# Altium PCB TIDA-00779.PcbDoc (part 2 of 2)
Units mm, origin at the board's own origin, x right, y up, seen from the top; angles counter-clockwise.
Board outline 200 x 145 mm, 2 copper layers (Top Layer, Bottom Layer), stack 1.57 mm thick; 147 components, 60 nets, 299 pads, 545 vias.
Unrouted connection lines stored in the file: 4.
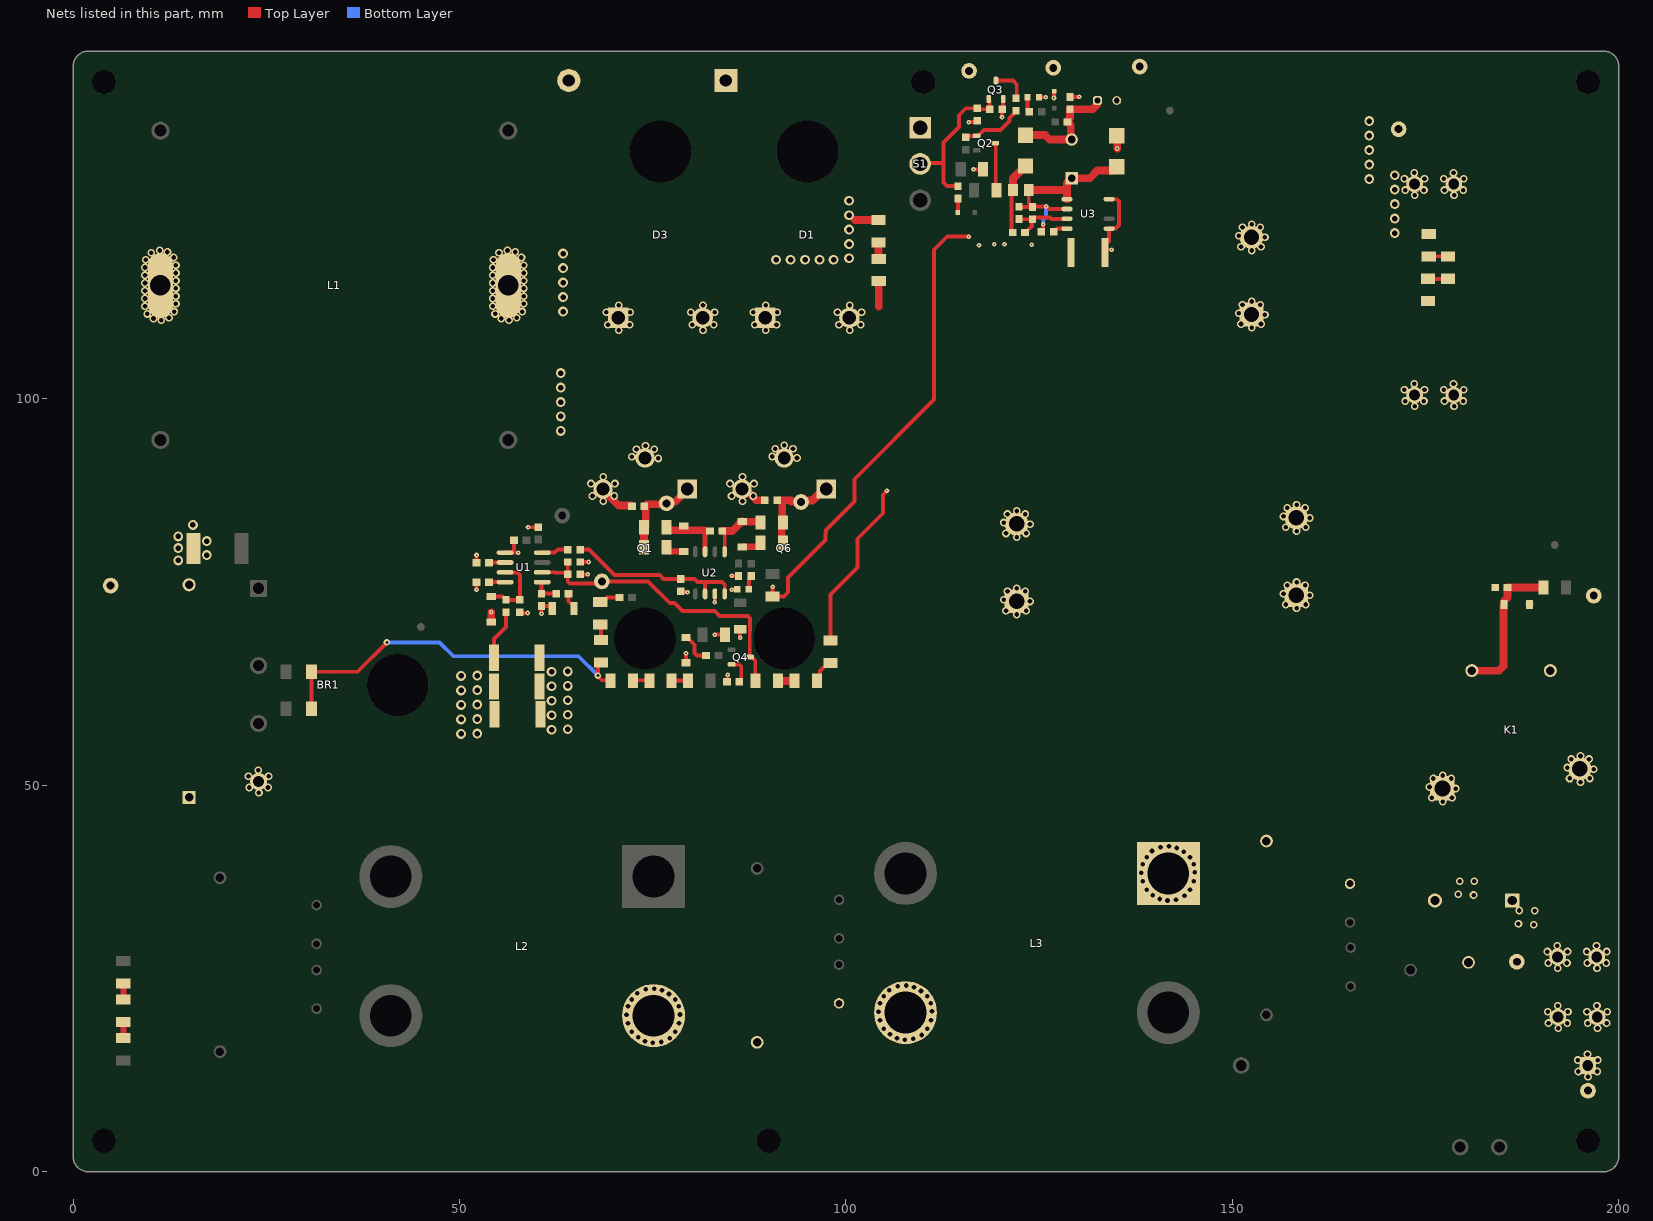
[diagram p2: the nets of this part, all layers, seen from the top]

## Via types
v1: diameter 1, hole 0.6, Top Layer to Bottom Layer, 423 vias
v2: diameter 1.27, hole 0.711, Top Layer to Bottom Layer, 82 vias
v3: diameter 0.6, hole 0.2, Top Layer to Bottom Layer, 38 vias
v4: diameter 0.864, hole 0.406, Top Layer to Bottom Layer, 2 vias

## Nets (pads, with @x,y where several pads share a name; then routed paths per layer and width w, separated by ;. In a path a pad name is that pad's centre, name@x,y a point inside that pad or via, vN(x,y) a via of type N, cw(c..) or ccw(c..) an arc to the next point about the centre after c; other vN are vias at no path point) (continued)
NetC2_2: C2.2 C6.2 L2.4 L3.3
  other v1: 75,16.7 76.1,16.8 74,16.9 107.6,17.1 108.7,17.2 77.2,17.3 106.6,17.3 73.1,17.4 109.8,17.7 105.7,17.8 72.3,18.1 77.9,18.1 104.9,18.5 110.5,18.5 71.8,19.2 78.4,19.2 104.4,19.6 111,19.6 71.6,20.3 71.6,20.3 78.53,20.354 104.2,20.7 104.2,20.7 111.13,20.754 71.8,21.4 78.38,21.404 104.4,21.8 110.98,21.804 72.3,22.3 77.9,22.3 104.9,22.7 110.5,22.7 77.1,23 73,23.1 109.7,23.4 76.2,23.5 105.6,23.5 74.1,23.6 75.2,23.7 108.8,23.9 106.7,24 107.8,24.1
NetC3_2: C3.2 D2.2 L1.S R2.2 TP3.1
  other v1: 11.4,110.2 10.4,110.4 12.4,110.5 9.6,111 13.1,111.3 9.3,112 13.3,112.3 9.3,113 13.3,113.3 9.3,114 13.3,114.3 9.3,115 13.3,115.3 9.3,116 13.3,116.3 9.3,117 13.3,117.3 9.4,118 13,118.3 10.1,118.9 12.2,119 11.2,119.2
  other v2: 13.6,79.1 17.3,79.8 13.6,80.7 17.3,81.6 13.6,82.2 15.5,83.7
NetC10_1: C10.1 U1.2 | length 2.1
  Top Layer w0.5: C10.1@53.8,78.8 53.818,78.817 55.882,78.817 U1.2@55.9,78.835
NetC13_1: C13.1 R10.2 U1.5 | length 3.4
  Top Layer w0.5: U1.5@60.6,76.295 60.6,74.775 60.625,74.8 R10.2@62.5,74.8
NetC14_2: C14.2 R10.1 | length 2.3
  Top Layer w0.5: R10.1@64.1,74.8 64.1,73.793 64.393,73.5 64.575,73.5 64.8,73.275 C14.2@64.8,72.9
NetC15_1: C15.1 D4.1 R11.1 U1.3 | length 9.1
  Top Layer w0.5: D4.1@54.1,74.437 55.588,74.437 56,74.025 R11.1@56,74 C15.1@57.8,74 57.8,77.2 57.454,77.546 55.919,77.546 U1.3@55.9,77.565
NetC17_1: C17.1 D10.1 K1.3 R33.2 | length 19.4
  Top Layer w1: K1.3@180.974,64.845 184.477,64.845 185.063,65.431 185.063,73.251 185.163,73.351 185.163,73.863 185.6,74.3 C17.1@185.6,75.6 R33.2@190.25,75.6
NetC21_2: C21.2 R28.1 | length 2.1
  Top Layer w1: C21.2@104.2,120.25 104.218,120.232 104.218,118.145 R28.1@104.236,118.127
NetC24_1: C24.1 Q3.1 R17.2 R19.1 S1.2 | length 20.5
  Top Layer w0.5: S1.2@109.6,130.4 109.7,130.5 112.6,130.5 ; R19.1@114.5,127.525 113.075,127.525 112.6,128 112.6,130.5 ; Q3.1@118.45,138.8 118.6,138.65 C24.1@118.6,137.475 117.125,137.475 R17.2@117,137.6 115.493,137.6 114.6,136.707 114.6,135.2 112.6,133.2 112.6,130.5
NetC27_1: C27.1 R43.2 U2.2 U2.4 | length 23.4
  Top Layer w0.5: R43.2@65.6,80.5 66.733,80.5 70.033,77.2 75.9,77.2 76.4,76.7 C27.1@78.6,76.7 80.424,76.7 80.806,76.318 81.538,76.318 ; U2.2@81.765,74.775 81.765,76.09 81.538,76.318 ; U2.4@84.305,74.775 84.305,75.995 83.982,76.318 81.538,76.318
NetC29_1: C29.1 R46.1 R47.2 U3.3 | length 8.5
  Top Layer w0.5: R47.2@122.377,123.264 122.391,123.25 124.109,123.25 C29.1@124.123,123.236 ; R46.1@123.164,121.523 123.189,121.523 124.043,122.377 124.043,123.157 C29.1@124.123,123.236 ; U3.3@128.598,123.301 126.56,123.301 126.4,123.461 124.348,123.461 C29.1@124.123,123.236
NetC29_2: C29.2 C30.2 C31.2 D15.1 L5.1 R47.1 U3.1 U3.2 | length 26.6
  Top Layer w0.5: R47.1@122.377,124.864 122.391,124.85 C29.2@124.109,124.85 ; C31.2@123.639,127.036 123.639,125.345 C29.2@124.123,124.861 ; C29.2@124.167,124.881 125.881,124.881 v3(125.9,124.9) 125.927,124.9 126.256,124.571 U3.2@128.598,124.571 ; C30.2@125.264,121.623 125.481,121.84 125.481,122.581 v3(125.5,122.6)
  Top Layer w1: C31.2@123.639,127.036 128.551,127.036 128.598,126.99 ; U3.1@128.598,125.841 128.598,126.99 ; D15.1@135.023,130.036 134.542,129.556 132.523,129.556 131.516,128.55 L5.1@129.197,128.55 128.598,127.95 128.598,126.99
  Bottom Layer w0.5: v3(125.5,122.6) 125.519,122.619 125.519,123.146 125.9,123.527 v3(125.9,124.9)
NetC30_1: C30.1 U3.4 | length 1.9
  Top Layer w0.5: C30.1@126.864,121.623 126.889,121.623 127.297,122.031 U3.4@128.598,122.031
NetC31_1: C31.1 D13.1 R46.2 | length 9.4
  Top Layer w0.5: R46.2@121.564,121.523 121.402,121.684 121.402,126.832 C31.1@121.607,127.036
  Top Layer w1: C31.1@121.607,127.036 121.607,128.52 D13.1@123.223,130.136
NetC32_1: C32.1 D13.2 L5.2 R48.2 R50.1 | length 14.5
  Top Layer w1: D13.2@123.223,134.136 125.778,134.136 126.364,133.55 L5.2@129.197,133.55 129.082,133.664 129.082,135.404 R50.1@128.664,135.823 ; R50.1@128.773,136.132 128.977,136.336 R48.2@128.977,137.464 131.891,137.464 132.477,138.05 132.477,138.547 C32.1@132.54,138.609
NetD1_2: D1.2 D3.2 L1.N Q1.2 Q6.2 R28.2 | length 3.3
  Top Layer w1: 104.236,111.936 R28.2@104.236,115.227
  other v1: 75.708,92.3 93.658,92.357 72.3,92.5 90.45,92.556 72.9,93.5 75.2,93.5 90.85,93.556 93.15,93.556 74.05,93.944 92,94 81.5,108.9 100.5,108.9 80.1,109.6 82.9,109.6 99.1,109.6 101.9,109.6 56.4,110.2 55.4,110.4 57.4,110.5 54.6,111 79.9,111.2 83,111.2 98.9,111.2 102,111.2 58.1,111.3 54.3,112 81.5,112.1 100.5,112.1 58.3,112.3 54.3,113 58.3,113.3 54.3,114 58.3,114.3 54.3,115 58.3,115.3 54.3,116 58.3,116.3 54.3,117 58.3,117.3 54.4,118 58,118.3 55.1,118.9 57.2,119 56.2,119.2
  other v2: 63.1,95.85 63.1,97.725 63.1,99.6 63.1,101.475 63.1,103.35 63.4,111.3 63.4,113.175 63.4,115.05 63.4,116.925 63.4,118.8
NetD5_1: D5.1 R13.2 | length 1.8
  Top Layer w0.5: D5.1@87.427,75.364 87.427,76.743 87.736,77.052 R13.2@87.736,77.077
NetD6_1: D6.1 D7.1 R20.2 R25.2 | length 49
  Top Layer w0.5: D7.1@30.85,59.9 D6.1@30.85,64.7 36.8,64.7 v4(40.6,68.5) ; R25.2@68.3,65.9 67.9,65.5 v4(67.9,64.2) 67.9,64.102 68.4,63.602 68.4,63.6 R20.2@69.55,63.6
  Bottom Layer w0.5: v4(40.6,68.5) 47.4,68.5 49.2,66.7 65.4,66.7 v4(67.9,64.2)
NetD8_2: D8.2 R23.1 | length 4.2
  Top Layer w0.5: D8.2@79.3,69.137 79.453,69.137 80.4,68.19 80.4,67.093 80.693,66.8 R23.1@81.9,66.8
NetD9_2: D9.2 R19.2 | length 1.8
  Top Layer w0.5: D9.2@114.466,124.125 114.5,124.159 R19.2@114.5,125.925
NetD11_1: D11.1 R3.1 R44.1 U2.7 | length 8
  Top Layer w0.6: 81.75,82.9 81.765,82.885 U2.7@81.765,80.225
  Top Layer w1: R3.1@76.75,83.4 76.75,83.15 76.9,83 81.65,83 81.75,82.9
NetD11_2: D11.2 R24.1 | length 2.6
  Top Layer w0.8: R24.1@76.75,80.8 76.75,80.525 77.013,80.262 D11.2@79,80.262
NetD12_1: D12.1 R40.1 R44.2 U2.5 | length 8.2
  Top Layer w0.5: R44.2@84,82.9 84.025,82.9 84.305,82.62 U2.5@84.305,80.225
  Top Layer w1: R44.2@84.025,82.9 85.295,82.9 86.533,84.138 D12.1@86.6,84.138 86.643,84.095 88.755,84.095 R40.1@88.85,84
NetD12_2: D12.2 R41.1 | length 2.7
  Top Layer w0.8: D12.2@86.6,80.863 88.688,80.863 88.95,81.125 R41.1@88.95,81.4
NetD16_1: D16.1 R31.1 | length 2
  Top Layer w0.5: D16.1@123.473,139.036 123.473,137.361 123.698,137.136 R31.1@123.723,137.136
NetF1_1: F1.1 P1.1 TP1.1
  other v1: 196.011,12.301 194.761,12.976 197.186,12.976 194.661,14.451 197.261,14.451 195.936,15.201 192.151,18.568 197.231,18.568 190.901,19.243 193.326,19.243 195.981,19.243 198.406,19.243 190.801,20.718 193.401,20.718 195.881,20.718 198.481,20.718 192.076,21.468 197.156,21.468
NetQ1_1: Q1.1 R1.2 R3.2 R24.2 TP7.1 | length 11.8
  Top Layer w1: R24.2@73.85,80.8 73.85,82.975 R3.2@73.85,83.4 ; R1.2@73.9,86.1 74,86.1 R1.2@74.1,86.2 ; R3.2@74.1,83.45 R1.2@74.1,86.2 ; Q1.1@79.45,88.239 77.894,86.682 76.98,86.682 76.664,86.367 74.267,86.367 R1.2@74.1,86.2
NetQ2_1: Q2.1 R15.2 R16.1 | length 8.3
  Top Layer w0.5: R15.2@115.5,133.85 115.65,134 116.85,134 Q2.1@116.9,134.05 117.1,134.05 117.85,134.8 120,134.8 121.168,135.968 121.168,136.343 122.1,137.275 R16.1@122.1,137.3
NetQ2_3: Q2.3 R18.1 | length 6.2
  Top Layer w0.5: Q2.3@119.3,133.09 Q2.3@119.3,133.1 119.325,133.1 119.375,133.05 119.375,127.075 R18.1@119.45,127
NetQ3_3: Q3.3 R16.2 | length 4.7
  Top Layer w0.5: Q3.3@119.4,141.2 121.6,141.2 122.1,140.7 R16.2@122.1,138.9
NetQ4_2: Q4.2 R14.2 | length 3.4
  Top Layer w0.5: Q4.2@85.2,65.65 86.157,65.65 86.45,65.357 86.45,63.625 86.225,63.4 R14.2@86.2,63.4
NetQ6_1: Q6.1 R40.2 R41.2 R42.2 TP4.1 | length 12
  Top Layer w1: R42.2@91.3,86.9 91.75,86.9 ; R40.2@91.7,83.844 91.7,81.55 R41.2@91.85,81.4 ; R40.2@91.75,84 91.75,86.9 ; 92.9,86.7 94.149,86.7 TP4.1@94.187,86.662 94.384,86.86 95.671,86.86 Q6.1@97.15,88.338 ; 92.9,86.9 91.75,86.9
NetR6_1: R6.1 R7.2 | length 3.2
  Top Layer w0.5: R7.2@96.25,63.5 96.65,63.9 96.65,64.775 97.725,65.85 R6.1@98,65.85
NetR7_1: R7.1 R8.2 | length 2.2
  Top Layer w1: R8.2@91.2,63.525 91.212,63.513 93.337,63.513 R7.1@93.35,63.5
NetR12_2: R12.2 U1.4 | length 2.1
  Top Layer w0.5: R12.2@53.8,76.3 53.802,76.297 55.898,76.297 U1.4@55.9,76.295
NetR20_1: R20.1 R21.2 | length 2.1
  Top Layer w0.5: R20.1@72.45,63.6 74.495,63.6 R21.2@74.552,63.544
NetR21_1: R21.1 R22.2 | length 2.1
  Top Layer w0.5: R21.1@77.452,63.544 79.494,63.544 R22.2@79.55,63.6
NetR25_1: R25.1 R26.2 | length 2.3
  Top Layer w0.5: R26.2@67.9,70.8 R26.2@68,70.9 ; R26.2@68.2,70.8 68.3,70.7 R25.1@68.3,68.8 R25.1@68.4,68.9
NetR26_1: R26.1 R38.2 | length 2.7
  Top Layer w0.5: R26.1@68.2,73.7 68.475,73.7 69.075,74.3 R38.2@70.7,74.3
NetR29_1: R29.1 R30.2 | length 2.1
  Top Layer w0.8: R29.1@6.5,17.3 R30.2@6.5,19.4
NetR30_1: R30.1 R32.2 | length 2.1
  Top Layer w0.8: R30.1@6.5,22.3 R32.2@6.5,24.35
NetR34_1: R34.1 R35.2 | length 2.5
  Top Layer w0.5: R34.1@175.4,118.45 R35.2@177.9,118.45
NetR35_1: R35.1 R36.2 | length 2.5
  Top Layer w0.5: R36.2@175.44,115.5 R35.1@177.94,115.5
NetR43_1: R43.1 U1.8 | length 3.6
  Top Layer w0.5: U1.8@60.6,80.105 62.305,80.105 62.7,80.5 R43.1@64,80.5
PGND: C4.1 C5.1 C10.2 C11.2 C12.2 C13.2 C14.1 C15.2 C16.2 C17.2 C18.1 C19.2 C20.2 C24.2 C25.2 C27.2 C28.1 C32.2 C33.1 D4.2 D5.2 D8.1 D10.2 D14.2 D15.2 D16.2 K1.4 P5.1 Q1.3 Q3.2 Q6.3 R1.1 R4.1 R5.1 R9.1 R12.1 R14.1 R17.1 R27.1 R36.1 R42.1 R45.1 R48.1 S1.1 TP6.1 TP10.1 TP11.1 TP12.1 U1.1 U2.3 | length 99.9
  Top Layer w0.5: v3(52.2,75.3) R12.1@52.2,76.3 ; C10.2@52.2,78.8 v3(52.2,79.8) ; U1.1@55.9,80.105 U1.1@56.905,80.105 ; U1.1@56.673,80.1 56.702,80.1 57.05,80.448 C12.2@57.05,81.7 ; 57.05,80.1 v3(57.6,80.1) ; C15.2@57.8,72.4 57.9,72.3 v3(58.8,72.3) ; v3(58.859,83.4) C16.2@60.2,83.4 ; v3(60.6,72.2) C13.2@60.6,73.2 61.775,73.2 62,72.975 C14.1@62,72.9 ; C11.2@65.6,77.3 v3(66.6,77.3) ; R9.1@65.6,78.9 v3(66.7,78.9) ; C27.2@78.6,75.1 78.681,75.019 79.481,75.019 v3(79.5,75) ; 79.3,66.4 v3(79.3,67.1) ; v3(83,69.5) C20.2@84.35,69.5 ; v3(83,73.7) 83.017,73.718 83.017,74.757 U2.3@83.035,74.775 ; R14.1@84.6,63.4 84.681,63.481 84.681,64.281 v3(84.7,64.3) ; v3(85.2,75.3) 85.219,75.319 85.883,75.319 D5.2@85.927,75.364 ; v3(85.2,77.1) C28.1@86.1,77.1 ; v3(86.3,69.1) C25.2@86.3,70.2 ; v3(90.5,75.7) R27.1@90.5,74.45 91.963,74.45 92.5,74.987 92.5,76.9 97.35,81.75 97.35,82.75 97.4,82.8 97.4,83.033 101.1,86.733 101.1,89.6 111.4,99.9 111.4,119.3 113.1,121 v3(115.9,121) ; v3(115.9,135.8) 115.919,135.819 116.819,135.819 R17.1@117,136 ; v3(116.5,129.7) C19.2@117.75,129.7 ; v3(120.19,136.465) 120.2,136.475 120.2,137.55 120.3,137.65 120.3,138.75 Q3.2@120.35,138.8 ; D16.2@124.973,139.036 v3(125.864,139.036) ; v3(126.909,138.931) 126.909,139.75 D14.2@126.959,139.8 ; R48.1@128.977,139.064 130.164,139.064 v3(130.2,139.1)
  Top Layer w1: D4.2@54.1,71.162 v3(54.1,72.4) ; Q1.3@68.55,88.239 70.588,86.2 72.2,86.2 R1.1@72.3,86.1 ; Q6.3@86.55,88.343 86.956,88.343 88.399,86.9 R42.1@89.5,86.9 ; D15.2@135.023,134.036 135.1,133.959 v3(135.1,132.4)
  other v1: 122.1,72.1 120.7,72.6 123.3,72.6 158.3,72.9 156.9,73.4 159.5,73.4 123.8,73.8 120.4,74 160,74.6 156.6,74.8 120.9,75.1 123.2,75.1 122.1,75.5 157.1,75.9 159.4,75.9 158.3,76.3 68.6,86.744 86.6,86.743 67.2,87.444 70,87.444 85.2,87.444 88,87.444 67,89.044 70.1,89.044 85,89.043 88.1,89.043 68.6,89.944 86.6,89.944 173.6,99.043 178.68,99.043 172.35,99.718 174.775,99.718 177.43,99.718 179.855,99.718 172.25,101.193 174.85,101.193 177.33,101.193 179.93,101.193 173.525,101.943 178.605,101.943 152.5,109.2 151.1,109.7 153.7,109.7 154.2,110.9 150.8,111.1 151.3,112.2 153.6,112.2 152.5,112.6
  other v2: 61.9,57.2 64,57.25 61.9,59.075 64,59.125 61.9,60.95 64,61 61.9,62.825 64,62.875 61.9,64.7 64,64.75
  other v3: 117.2,119.9 124.041,119.959 119.2,120 120.5,120
RLY-N: C1.1 C9.2 K1.1 L3.1 RT1.2 | length 12.3
  Top Layer w0.254: K1.1@175.845,48.357 176.039,48.551 v1@176.039,47.955 ; K1.1@177.164,49.605 178.245,49.605 K1.1@178.345,49.705 ; K1.1@177.199,49.605 177.245,49.559 v1@177.245,47.857 ; K1.1@177.245,49.605 v1@177.245,51.257 ; K1.1@178.445,49.705 178.797,49.705 v1@178.945,49.557
  Bottom Layer w0.254: v1@177.245,47.857 177.174,47.786 177.174,49.595 K1.1@177.164,49.605 178.245,49.605 K1.1@178.345,49.705 ; K1.1@177.245,49.605 v1@177.245,51.257 ; K1.1@178.445,49.705 178.797,49.705 v1@178.945,49.557 ; K1.1@176.039,48.551 175.845,48.357 K1.1@176.039,48.551 ; K1.1@176.039,48.551 176.039,48.709 K1.1@176.039,48.551
  other v1: 141.6,35.1 142.7,35.2 140.6,35.3 143.8,35.7 139.7,35.8 181.2,35.8 179.2,35.9 138.9,36.5 144.5,36.5 138.4,37.6 145,37.6 179.4,37.6 181.3,37.6 138.2,38.7 138.2,38.7 145.13,38.754 138.4,39.8 144.98,39.804 138.9,40.7 144.5,40.7 143.7,41.4 139.6,41.5 142.8,41.9 140.7,42 141.8,42.1 177.2,47.882 175.8,48.382 178.4,48.382 178.9,49.582 175.5,49.782 176,50.882 178.3,50.882 177.2,51.282
RLY-P: K1.2 P2.1 RT1.1 RV1.1 TP2.1 | length 15.4
  Top Layer w0.254: v1(193.625,50.897) 193.66,50.897 K1.2@193.866,51.103 ; v1@193.819,50.495 193.866,50.542 K1.2@193.866,51.103 ; v1(195.025,50.397) 194.984,50.357 194.984,52.104 K1.2@194.944,52.145 ; v1(195.025,53.797) 194.984,53.757 194.984,52.316 194.984,52.186 K1.2@194.944,52.145 ; K1.2@195.044,52.316 v1(196.125,53.397) ; K1.2@193.866,51.103 194.908,52.145 K1.2@194.944,52.145
  Bottom Layer w0.254: v1(193.625,50.897) 193.66,50.897 K1.2@193.866,51.103 ; v1@193.819,50.495 193.866,50.542 K1.2@193.866,51.103 ; v1(195.025,50.397) 194.984,50.357 194.984,50.211 194.984,52.104 K1.2@194.944,52.145 ; v1(195.025,53.797) 194.984,53.757 194.984,52.316 194.984,52.186 K1.2@194.944,52.145 ; K1.2@195.044,52.316 v1(196.125,53.397) ; K1.2@193.866,51.103 194.908,52.145 K1.2@194.944,52.145
  other v1: 192.1,26.343 197.18,26.343 190.85,27.018 193.275,27.018 195.93,27.018 198.355,27.018 190.75,28.493 193.35,28.493 195.83,28.493 198.43,28.493 192.025,29.243 197.105,29.243 189,31.98 187,32.08 189.1,33.78 187.1,33.8 196.225,50.897 196.725,52.097 193.325,52.297 193.825,53.397
RTN: BR1.4 C3.1 R4.2 R5.2 R11.2 R45.2 | length 6.5
  Top Layer w0.5: R45.2@54.45,66.5 54.45,68.95 56,70.5 R11.2@56,72.4
  other v1: 24.04,49.043 22.79,49.718 25.215,49.718 22.69,51.193 25.29,51.193 23.965,51.943
  other v2: 50.2,56.65 52.3,56.7 50.2,58.525 52.3,58.575 50.2,60.4 52.3,60.45 50.2,62.275 52.3,62.325 50.2,64.15 52.3,64.2
VDCBUS: C4.2 C5.2 C18.2 C21.1 C33.2 D1.1 D2.1 D3.1 P4.1 R6.2 R34.2 TP5.1 U3.5 U3.8 | length 36
  Top Layer w0.5: R6.2@98,68.75 98,74.7 101.5,78.2 101.5,81.9 104.8,85.2 104.8,87.6 v3(105.3,88.1) ; C33.2@133.523,118.436 133.523,119.886 134.048,120.411 U3.5@134.048,122.031 134.067,122.05 134.85,122.05 135.3,122.5 135.3,125.548 135.007,125.841 U3.8@134.048,125.841 ; C33.2@133.523,119.1 133.723,119.3 v3(134.4,119.3)
  Top Layer w1: 101.17,123.15 C21.1@104.2,123.15
  other v1: 122.1,82.1 120.7,82.6 123.3,82.6 158.3,82.9 156.9,83.4 159.5,83.4 123.8,83.8 120.4,84 160,84.6 156.6,84.8 120.9,85.1 123.2,85.1 122.1,85.5 157.1,85.9 159.4,85.9 158.3,86.3 70.6,108.9 89.6,108.9 69.2,109.6 72,109.6 88.2,109.6 91,109.6 69,111.2 72.1,111.2 88,111.2 91.1,111.2 70.6,112.1 89.6,112.1 152.5,119.2 151.1,119.7 153.7,119.7 154.2,120.9 150.8,121.1 151.3,122.2 153.6,122.2 152.5,122.6 173.6,126.343 178.68,126.343 172.35,127.018 174.775,127.018 177.43,127.018 179.855,127.018 172.25,128.493 174.85,128.493 177.33,128.493 179.93,128.493 173.525,129.243 178.605,129.243
  other v2: 90.95,118 92.825,118 94.7,118 96.575,118 98.4,118 100.4,118.2 100.4,120.025 171,121.45 100.4,121.9 171,123.325 100.4,123.775 171,125.2 100.4,125.65 171,127.075 167.7,128.45 171,128.95 167.7,130.325 167.7,132.2 167.7,134.075 167.7,135.95
VSENSE: C11.1 Q4.3 R8.1 R9.2 TP8.1 U1.6 | length 40.4
  Top Layer w0.5: U1.6@60.6,77.565 62.335,77.565 62.4,77.5 63.8,77.5 C11.1@64,77.3 ; R9.2@64,78.9 C11.1@64,77.3 ; R8.1@88.3,63.525 88.25,63.575 88.25,66.15 87.8,66.6 Q4.3@87.6,66.6 87.55,66.65 87.55,70 87.6,70.05 87.6,71.613 87.307,71.906 83.655,71.906 83.017,72.543 78.857,72.543 77.8,73.6 77.19,73.6 74.405,76.385 TP8.1@68.417,76.385 68.133,76.1 64.293,76.1 64,76.393 C11.1@64,77.3
pads on no net: BR1. D1. D3. FID1.1 FID2.1 FID3.1 L1.1 L1.2 L1.3 L1.4 MP1. MP2. MP3. MP4. MP5. MP6. Q1. Q6. S1.3 U2.1 U2.8 U3.6

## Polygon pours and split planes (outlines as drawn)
RLY-N on Bottom Layer "Bottom Layer-RLY-N" (solid, pour order 147): 179.3,35.3 181.6,35.3 186,39.7 186,53.9 183.8,56.1 144.5,56.1 136,47.6 136,34.8 136.5,34.3 160.7,34.3 161.7,35.3 169,35.3 170.7,33.6 177.6,33.6
NetBR1_2 on Bottom Layer "Bottom Layer-NetBR1_2" (solid, pour order 143): 25.85,63 36.3,63 37.3,64 37.3,68.1 35.1,70.3 21,70.3 3.6,70.3 2.2,70.3 0.9,69 0.9,66.8 1.7,66 18.05,66 21.05,63 25.85,63
VDCBUS on Bottom Layer "Bottom Layer-VDCBUS 1" (solid, pour order 139): 67.6,108.5 74.2,108.5 74.4,108.3 75.1,109 75.1,113.2 77.9,116 85.4,116 86.2,115.2 86.2,108.494 87.794,106.9 93.2,106.9 93.8,107.5 93.8,112.7 97.1,116 101.4,116 104.6,112.8 104.6,106.1 102.9,104.4 107,104.4 108.2,103.2 115,103.2 128,116.2 113.8,116.2 105.136,124.864 101.7,128.3 101.7,141.7 100.1,143.3 73.9,143.3 70.3,139.7 70.3,132.539 67.6,129.839
PGND on Bottom Layer "Bottom Layer-PGND 1" (solid, pour order 119): 152.5,60.1 152.6,60 195.2,60 199,63.8 199,75.8 198.1,76.7 175,76.7 108,76.7 98.1,86.6 95.4,86.6 95.2,86.8 95.2,87.8 94.9,88.1 94.6,88.1 94.4,88.3 90,88.3 87.8,90.5 82.2,90.5 81.7,90 81.7,87.4 80.7,86.4 78.5,86.4 78,86.9 78,88 77.4,88.6 71.7,88.6 69.4,90.9 66.9,90.9 66,90 66,78.6 67.5,77.1 84.3,77.1 88.9,72.5 95.4,72.5 104.8,63.1 66.2,63.1 63.5,65.8 58,65.8 57.8,65.6 57.8,53.6 58.4,53 133.9,53 141,60.1
RLY-P on Bottom Layer "Top Layer-RLY-P" (solid, pour order 129): 184.577,25.575 191.777,25.575 198.677,25.575 199.7,26.597 199.7,54.8 197.6,56.9 188.3,56.9 187.577,56.177 187.577,38.475 182.477,33.375 179.975,33.375 177.677,31.077 177.677,27.623 179.077,26.223 179.725,25.575
NetC1_2 on Bottom Layer "Top Layer-NetC1_2" (solid, pour order 128): 171.577,5.475 177.077,10.975 177.077,23.375 175.777,24.675 136.977,24.675 135.877,23.575 135.877,10.375 140.777,5.475
PGND on Bottom Layer "TOP_LAYER_NONET_P-001" (solid, remove dead copper, pour order 79): 105.7,129.6 115.9,119.4 125.8,119.4 129.7,123.3 129.7,125.014 132.386,127.7 135,127.7 140.7,133.4 140.7,143.2 139.4,144.5 109.1,144.5 105.7,141.1 105.7,138.7
NetD1_2 on Bottom Layer "TOP_LAYER_NONET_P-001" (solid, pour order 134): 97.077,112.575 97.677,113.175 102.477,113.175 103,112.652 103,107.6 102.5,107.1 97.7,107.1 97.077,107.723
NetD1_2 on Bottom Layer "TOP_LAYER_NONET_P-001" (solid, pour order 133): 78.077,112.575 78.677,113.175 83.477,113.175 84,112.652 84,107.6 83.5,107.1 78.7,107.1 78.077,107.723
NetD1_2 on Bottom Layer "TOP_LAYER_NONET_P-001" (solid, pour order 132): 36.118,119.616 36.118,92.933 38.377,90.675 38.403,90.7 62.5,90.7 64.6,92.8 64.6,120.3 62.4,122.5 62.375,122.475 38.977,122.475
NetC3_2 on Bottom Layer "Bottom Layer-No Net 2" (solid, pour order 126): 14.303,143.9 65.927,143.9 67.377,142.313 67.377,134.682 59.926,127.375 31.784,127.375 29.132,124.888 29.236,87.534 26.634,84.931 19.765,84.885 18.377,83.596 18.377,74.658 17.277,73.375 3.677,73.375 2.677,74.375 2.677,132.275
NetF1_1 on Bottom Layer "TOP_LAYER_NONET_P-001" (solid, pour order 127): 179,22 179,8.5 179.525,7.975 198.777,7.975 199.777,8.975 199.777,22.775 199.277,23.275 180.275,23.275
NetC2_1 on Bottom Layer "M1 Board Outline-No Net" (solid, pour order 123): 109.7,50.4 113.077,47.023 113.077,33.975 110.977,31.875 70.477,31.875 68.577,33.775 68.577,48.577 70.4,50.4
NetC2_2 on Bottom Layer "Top Layer-No Net 5" (solid, remove dead copper, pour order 49): 72.4,0.9 108.7,0.9 112.9,5.1 112.9,23.1 111,25 104.9,25 102.1,22.2 91.9,22.2 89.1,25 71.4,25 69,22.6 69,4.3
GNDE on Bottom Layer "TOP_LAYER_NONET_P-001" (solid, pour order 121): 177.1,1 175.8,2.3 178.5,5 186.9,5 188.3,3.6 188.3,1.5 187.8,1
VDCBUS on Bottom Layer "Bottom Layer-VDCBUS" (solid, pour order 115): 186.6,79.8 191.6,84.8 191.6,125.3 180,136.9 147.8,136.9 116.4,105.5 95.7,105.5 93.8,107.4 93.8,112.8 93.2,113.4 86.9,113.4 86.1,112.6 86.1,109.194 87.2,108.094 87.2,105.6 87,105.4 75.5,105.4 75.1,105.8 75.1,112.2 73.4,113.9 68.3,113.9 67.6,113.2 67.6,99.1 70,96.7 95.3,96.7 111.8,80.2 112.2,79.8
PGND on Bottom Layer "Bottom Layer-PGND" (solid, remove dead copper, pour order 98): 109.675,62.775 111.5,64.6 111.5,66.8 107.7,66.8 96.4,78.1 68.3,78.1 67,79.4 67,86.3 66.6,86.7 60.2,86.7 59.5,86 59.5,84.4 59,83.9 50.1,83.9 49.2,83 49.2,70.8 51.5,68.5 65.5,68.5 69.5,64.5 69.5,62.39 69.79,62.1 72,62.1 72,62.5 71.725,62.775
NetBR1_1 on Bottom Layer "NETBR1_1_L02_P084" (solid, pour order 84): 18.6,74.6 20.1,73.1 43.4,73.1 45.7,75.4 45.7,82.2 44.4,83.5 19.3,83.5 18.6,82.8
RTN on Bottom Layer "Top Layer-No Net 1" (solid, pour order 44): 19.8,53.1 26.4,53.1 30.3,57 43,57 44.1,57 46.2,59.1 46.2,64.5 46.9,65.2 56.8,65.2 56.8,49.5 53.1,45.8 50.4,45.8 14.8,45.8 13.5,47.1 13.5,52.3 14.3,53.1 16.4,53.1
NetBR1_3 on Bottom Layer "Bottom Layer-No Net 4" (solid, pour order 42): 37.9,23.4 44.7,23.4 46.7,21.4 46.7,2.4 45.2,0.9 13.9,0.9 0.9,13.9 0.9,62.9 1.9,63.9 15.9,63.9 19.8,60 25.7,60 26.3,59.4 26.3,56.4 25.2,55.3 12.5,55.3 10.6,53.4 10.6,46.8 14.9,42.5 14.9,31.8 26.9,19.8 34.3,19.8
NetBR1_2 on Bottom Layer "Bottom Layer-No Net 3" (solid, pour order 41): 18.6,43.4 45.8,43.4 46.6,42.6 46.6,35.7 44,33.1 18.7,33.1 17,34.8 17,41.8
RLY-N on Top Layer "Top Layer-RLY-N" (solid, pour order 146): 179.3,35.3 181.5,35.3 186,39.8 186,53.9 183.9,56 144.4,56 136,47.6 136,34.1 136.7,33.4 159.8,33.4 161.7,35.3 169,35.3 170.7,33.6 177.6,33.6
PGND on Top Layer "TOP_LAYER_NONET_P-001" (solid, pour order 140): 181.7,60 195.2,60 199,63.8 199,72.6 198.5,73.1 189.1,73.1 187.2,75 187.2,80.8 185.9,82.1 180.3,82.1 178.6,80.4 178.6,61.1 179.3,60.4
NetD1_2 on Top Layer "Bottom Layer-No Net 1" (solid, pour order 125): 92.977,90.875 98.277,96.175 100.477,96.175 106.977,102.675 106.977,112.475 105.477,113.975 97.677,113.975 96.277,112.575 96.277,107.375 94.277,105.375 85.977,105.375 83.977,107.375 83.977,112.675 83.477,113.175 78.677,113.175 78.077,112.575 78.077,106.775 76.577,105.275 66.077,105.275 64.577,106.775 64.577,114.775 64.577,117.811 64.577,120.275 62.377,122.475 52.577,122.475 38.977,122.475 36.118,119.616 36.237,92.814 38.377,90.675 72.677,90.675 74.877,90.675 77.477,93.275 88.177,93.275 90.577,90.875
PGND on Top Layer "TOP_LAYER_NONET_P-001" (solid, pour order 136): 177.3,113.3 188.4,113.3 192.4,109.3 192.4,85.6 186.3,79.5 183.9,79.5 182.1,77.7 181.1,78.7 179,78.7 179,108.6 177.4,110.2
PGND on Top Layer "Top Layer-PGND" (solid, pour order 117): 182.9,78 182.9,108.1 181.1,109.9 177.7,113.3 171.3,113.3 166.1,118.5 166.1,123.4 155.7,133.8 144.8,133.8 139,128 139,117.5 135.7,114.2 130.3,114.2 129.5,115 129.5,120.1 129.1,120.5 117.2,120.5 113.1,116.4 113.1,88.2 105.8,80.9 105.8,72.739 105.7,72.7 105.8,72.6 105.8,64.668 101.392,61.8 67.6,61.8 65.7,63.7 65.7,68.2 58.8,68.2 57.8,67.2 57.8,53.5 58.5,52.8 133.8,52.8 141,60 181.7,60 182.9,61.2
RLY-P on Top Layer "Top Layer-RLY-P" (solid, pour order 104): 184.5,25.6 191.7,25.6 198.6,25.6 199.7,26.7 199.7,54.8 197.6,56.9 188.1,56.9 187.5,56.3 187.5,38.5 182.4,33.4 180,33.4 177.6,31 177.6,27.7 179,26.3 179.7,25.6
NetBR1_3 on Top Layer "TOP_LAYER_NONET_P-001" (solid, pour order 131): 25.7,60 26.3,59.4 26.3,57 24.6,55.3 20.1,55.3 19.3,56.1 19.3,59.5 19.8,60
NetC2_2 on Top Layer "Top Layer-No Net 5" (solid, remove dead copper, pour order 124): 72.477,0.875 108.777,0.875 112.977,5.075 112.977,23.075 111.077,24.975 104.977,24.975 102.177,22.175 91.977,22.175 89.177,24.975 71.477,24.975 69.077,22.575 69.077,4.275
GNDE on Top Layer "TOP_LAYER_NONET_P-001" (solid, pour order 122): 182.45,1 187.8,1 188.3,1.5 188.3,3.6 186.9,5 177.9,5 177.1,4.2 177.1,1.3 177.4,1
VDCBUS on Top Layer "Top Layer-VDCBUS" (solid, pour order 110): 95,116.1 100.3,116.1 101.7,117.5 101.7,141.7 100.1,143.3 73.9,143.3 70.3,139.7 70.3,132.539 67.7,129.939 67.7,109 68.5,108.2 74.3,108.2 75,108.9 75,114.3 76.6,115.9 85.6,115.9 86.1,115.4 86.1,109.2 87,108.3 92.1,108.3 93,109.2 93,114.1
NetC1_2 on Top Layer "Top Layer-NetC1_2" (solid, pour order 101): 171.5,5.5 177,11 177,23.4 175.7,24.7 136.9,24.7 135.8,23.6 135.8,10.4 140.7,5.5
VDCBUS on Top Layer "TOP_LAYER_NONET_P-001" (solid, pour order 102): 170.6,120.7 169.7,121.6 169.7,124.9 165.6,129 165.6,135.6 166.87,136.87 180.03,136.87 187,129.9 187,123.1 184.6,120.7
NetF1_1 on Top Layer "TOP_LAYER_NONET_P-001" (solid, pour order 99): 179,22 179,8.5 179.5,8 198.7,8 199.7,9 199.7,22.8 199.2,23.3 180.3,23.3
NetBR1_1 on Top Layer "TOP_LAYER_NONET_P-001" (solid, pour order 90): 18.6,74.6 20.1,73.1 43.4,73.1 45.7,75.4 45.7,82.2 44.4,83.5 19.3,83.5 18.6,82.8
NetC3_2 on Top Layer "Bottom Layer-No Net 2" (solid, pour order 87): 14.05,143.75 65.927,143.9 67.377,142.313 67.377,134.682 59.926,127.375 31.784,127.375 29.132,124.888 29.236,87.534 26.634,84.931 19.765,84.885 18.377,83.596 18.377,74.773 17.2,73.4 3.6,73.4 2.6,74.4 2.6,132.3
RTN on Top Layer "Top Layer-No Net 1" (solid, pour order 83): 19.8,53.1 28,53.1 31.9,57 43,57 44.1,57 46.2,59.1 46.2,67.8 46.6,68.2 56.9,68.2 56.9,49.4 53.5,46 53.3,45.8 50.4,45.8 14.8,45.8 13.5,47.1 13.5,52.3 14.3,53.1 16.4,53.1
NetBR1_2 on Top Layer "Top Layer-NetBR1_2" (solid, pour order 74): 0.9,27.5 1.7,26.7 21.45,26.7 23.6,28.85 23.6,28.9 28.1,33.4 44.3,33.4 46.6,35.7 46.6,42.6 45.8,43.4 14,43.4 10.6,46.8 10.6,53.4 20.2,63 25.9,63 26.4,63.5 26.4,69.6 25.8,70.2 23.8,70.3 2.2,70.3 0.9,69
NetBR1_3 on Top Layer "Top Layer-No Net 12" (solid, pour order 59): 38.2,22.9 15.6,22.9 11.5,18.8 11.5,3.4 14,0.9 45.2,0.9 46.7,2.4 46.7,21.5 44.8,23.4 38.7,23.4
NetC2_1 on Top Layer "M1 Board Outline-No Net" (solid, pour order 48): 109.6,50.5 113,47.1 113,34 110.9,31.9 70.4,31.9 68.5,33.8 68.5,48.5 70.5,50.5

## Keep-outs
Bottom Layer:
  circle w0.254: c129.197,128.55 r1.5
Keep-Out Layer:
  circle w0.254: c196,4 r4
  circle w0.254: c196,141 r4
  circle w0.254: c4,141 r4
  circle w0.254: c4,4 r4
  circle w0.254: c90,4 r4
  circle w0.254: c110,141 r4
  lines w0.254: -0.127,87.63 cw(c0,87.63) 0,87.757 ccw(c0,87.63) -0.127,87.63

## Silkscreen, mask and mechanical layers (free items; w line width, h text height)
Top Overlay:
  text "BIAS" at 122,143.7 h0.8
  text "GND" at 117.7,142.6 h0.8
  text "GND" at 128.9,142.6 h0.8
  text "LED" at 122.1,142.5 h0.8
  text "GND" at 139.6,142.1 h0.8
  text "TIDA-00779" at 152.16,138.5 h3
  text "Rev D" at 167.4,138.5 h3
  text "20240508" at 153.3,136 h1.5
  text "PFC" at 103.3,134.5 h0.8
  text "OFF" at 103.3,133 h0.8
  text "380VDC" at 170.8,130.8 h3
  text "PFC" at 103.4,126.7 h0.8
  text "ON" at 103.4,125.4 h0.8
  text "PGND" at 172.8,94.8 h3
  text "15V" at 64.1,86.5 h0.8
  text "PGND" at 194,78.8 h1.5
  text "Vs" at 70.7,78.7 h0.8
  text "15V" at 92.6,74.1 h0.8
  text "LED" at 92.7,73.1 h0.8
  text "TIDA-00779" at 152.8,56.4 h3
  text "Rev D" at 156,53.3 h3
  text "20240508" at 153.7,50.7 h1.5
  text "N" at 188.1,29 h3
  text "L" at 187.7,18.9 h3
  text "E" at 172,2.4 h3
Top Paste:
  text ".Layer_Name" at 14.656,-21.806 h0.8
Bottom Paste:
  text ".Layer_Name" at 14.656,-21.806 h0.8
Top Solder:
  rectangle: 16.4,78.5 20.9,82.8
Bottom Solder:
  drawing of 501 lines, arcs and shapes, not listed
  text "Layer" at 200.166,171.414 h1.52
  text "Name" at 210.578,171.414 h1.52
  text "Material" at 234.194,171.414 h1.52
  text "Thickness" at 256.032,171.414 h1.52
  text "Constant" at 272.537,171.414 h1.52
  text "Top Overlay" at 210.578,168.366 h1.52
  text "Top Solder" at 210.578,165.318 h1.52
  text "Solder Resist" at 234.194,165.318 h1.52
  text "0.010mm" at 256.032,165.318 h1.52
  text "3.5" at 272.537,165.318 h1.52
  text "1" at 200.166,162.27 h1.52
  text "Top Layer" at 210.578,162.27 h1.52
  text "0.036mm" at 256.032,162.27 h1.52
  text "Dielectric1" at 210.578,159.222 h1.52
  text "Core-043" at 234.194,159.222 h1.52
  text "1.499mm" at 256.032,159.222 h1.52
  text "4.3" at 272.537,159.222 h1.52
  text "2" at 200.166,156.174 h1.52
  text "Bottom Layer" at 210.578,156.174 h1.52
  text "0.036mm" at 256.032,156.174 h1.52
  text "Bottom Solder" at 210.578,153.126 h1.52
  text "Solder Resist" at 234.194,153.126 h1.52
  text "0.010mm" at 256.032,153.126 h1.52
  text "3.5" at 272.537,153.126 h1.52
  text "Bottom Overlay" at 210.578,150.078 h1.52
Drill Guide:
  text ".Layer_Name" at 14.656,-21.806 h0.8
M1 Board Outline:
  lines w0.2: 0,2 ccw(c2,2) 2,0 198,0 ccw(c198,2) 200,2 200,143 ccw(c198,143) 198,145 2,145 ccw(c2,143) 0,143 0,2
  lines w1: 64.6,89.5 64.6,89.6 66.8,91.8 69.7,91.8 71.9,89.6 75.5,89.6 77.8,91.9 87.8,91.9 90.3,89.4 93.9,89.4 97.5,93 ; 76.4,107.3 76.4,113.2 ; 76.5,113.4 77.9,114.8 84.1,114.8 85.1,113.8 85.1,108 ; 95.1,107.5 95.1,112.8 97.1,114.8 101,114.8
M2 Board Dimensions:
  rectangle: 3.175,-10.16 12.7,-6.985
  rectangle: 0,-6.985 3.175,-3.81
  lines w0.178: 0,-6.985 25.4,-6.985 ; 3.175,-10.16 3.175,-3.81 ; 6.35,-10.16 6.35,-3.81 ; 12.7,-10.16 12.7,-3.81 ; 19.05,-10.16 19.05,-3.81 ; 0,-10.16 0,-3.81 25.4,-3.81 25.4,-10.16 0,-10.16
  text ".Layer_Name" at 14.656,-21.806 h0.8
M3 3D STEP Top:
  text ".Layer_Name" at 14.656,-21.806 h0.8
M4 3D STEP Bottom:
  text ".Layer_Name" at 14.656,-21.806 h0.8
M5 Assembly Top:
  lines w0.254: -7.417,-23.626 160.223,-23.626 ; -7.417,-18.462 160.274,-18.462 ; -7.417,-13.297 -7.417,-28.791 94.31,-28.791 160.274,-28.791 160.274,-13.297 -7.404,-13.297 -7.404,-28.791 32.614,-28.791 ; 55.194,-28.791 55.194,-13.297 ; 87.376,-18.462 87.376,-13.297 ; 108.712,-18.462 108.712,-13.297 ; 124.511,-28.956 124.511,-23.804
  text "COMPONENTS MARKED 'DNP' SHOULD NOT BE POPULATED." at 29.299,-8.09 h0.8
  text "ASSEMBLY VARIANT:" at 29.286,-11.024 h0.8
  text ".VariantName" at 55.601,-11.024 h0.8
  text "PCB VIEWED FROM TOP SIDE" at -5.804,-16.654 h0.8
  text "BOARD #:" at 57.099,-16.654 h0.8
  text ".PRJ_Number" at 70.955,-16.654 h0.8
  text "REV:" at 92.405,-16.654 h0.8
  text "B" at 99.809,-16.654 h0.8
  text "SVN REV:" at 113.69,-16.654 h0.8
  text ".VersionControl_RevNumber" at 126.543,-16.654 h0.8
  text "TID #:" at 57.099,-21.819 h0.8
  text "TIDA-00779" at 70.955,-21.819 h0.8
  text "PLOT NAME =" at -5.804,-27.034 h0.8
  text ".plot_File_Name" at 14.656,-27.034 h0.8
  text "GENERATED    :" at 57.15,-27.034 h0.8
  text ".Print_Date" at 79.235,-27.034 h0.8
  text ".Print_Time" at 97.752,-27.034 h0.8
  text "TEXAS INSTRUMENTS" at 129.87,-27.034 h0.8
M6 Assembly Bottom:
  lines w0.254: -7.429,-18.474 160.261,-18.474 ; -7.379,-23.639 160.261,-23.639 ; 28.334,-28.969 28.334,-23.817 ; 44.133,-18.474 44.133,-13.31 ; 65.468,-18.474 65.468,-13.31 ; 97.65,-28.804 97.65,-13.31 ; 120.231,-28.804 160.249,-28.804 160.249,-13.31 -7.429,-13.31 -7.429,-28.804 58.534,-28.804 160.261,-28.804 160.261,-13.31
  text "COMPONENTS MARKED 'DNP' SHOULD NOT BE POPULATED." at 154.991,-8.077 h0.8
  text ".VariantName" at 128.473,-11.024 h0.8
  text "ASSEMBLY VARIANT:" at 154.864,-11.024 h0.8
  text ".VersionControl_RevNumber" at 26.302,-16.667 h0.8
  text "SVN REV:" at 39.154,-16.667 h0.8
  text ".PCB_Rev" at 53.035,-16.667 h0.8
  text "REV:" at 60.439,-16.667 h0.8
  text ".PRJ_Number" at 81.89,-16.667 h0.8
  text "BOARD #:" at 95.745,-16.667 h0.8
  text "PCB VIEWED FROM BOTTOM SIDE" at 158.648,-16.667 h0.8
  text ".TID" at 81.89,-21.831 h0.8
  text "TID #:" at 95.745,-21.831 h0.8
  text "TEXAS INSTRUMENTS" at 22.974,-27.047 h0.8
  text ".Print_Time" at 55.093,-27.047 h0.8
  text ".Print_Date" at 73.609,-27.047 h0.8
  text "GENERATED    :" at 95.694,-27.047 h0.8
  text ".plot_File_Name" at 138.189,-27.047 h0.8
  text "PLOT NAME =" at 158.648,-27.047 h0.8
M9 Title Sheet:
  drawing of 57 lines, arcs and shapes, not listed
  text "1" at 18.792,204.127 h1.78
  text "2" at 82.182,204.127 h1.78
  text "3" at 145.411,204.127 h1.78
  text "4" at 209.08,204.127 h1.78
  text "5" at 272.555,204.127 h1.78
  text "6" at 336.182,204.127 h1.78
  text "A" at -10.579,175.095 h1.78
  text "A" at 365.341,175.095 h1.78
  text "B" at -10.579,114.643 h1.78
  text "B" at 365.341,114.643 h1.78
  text "C" at -10.579,54.318 h1.78
  text "C" at 365.341,54.318 h1.78
  text "PROJECT TITLE:" at 288.125,7.048 h1.14
  text "TIDA-00779" at 289.395,3.662 h1.78
  text "DESIGNED FOR:" at 288.125,-0.597 h1.14
  text "D" at -10.579,-5.88 h1.78
  text "D" at 365.341,-5.88 h1.78
  text "FILE NAME:" at 288.125,-8.217 h1.14
  text "High Efficiency and Competitive 3k5w PFC" at 289.395,-11.265 h1.78
  text "Texas Instruments (TI) and/or its licensors do not warrant the accuracy or completeness of this specification" at 161.9,-15.376 h1.14
  text "ENGINEER:" at 288.125,-15.583 h1.14
  text "LAYOUT BY:" at 326.352,-15.583 h1.14
  text "or any information contained therein. TI and/or its licensors do not warrant that this design will meet" at 160.757,-18.237 h1.14
  text "Yuan Tao" at 289.7,-19.1 h1.78
  text "Yuan Tao" at 327.94,-19.1 h1.78
  text "the specifications, will be suitable for your application or fit for any particular purpose, or will operate in" at 160.757,-21.099 h1.14
  text "ALTIUM DESIGNER VERSION:" at 326.352,-23.457 h1.14
  text "an implementation. TI and/or its licensors do not warrant that the design is production worthy. You should" at 160.757,-23.961 h1.14
  text "completely validate and test your design implementation to confirm the system functionality for your application." at 161.9,-26.822 h1.14
  text ".print_Scale" at 289.395,-26.843 h1.78
  text ".Application_BuildNumber" at 327.635,-26.843 h1.78
  text "1" at 18.792,-32.093 h1.78
  text "2" at 82.182,-32.093 h1.78
  text "3" at 145.411,-32.093 h1.78
  text "4" at 209.08,-32.093 h1.78
  text "5" at 272.555,-32.093 h1.78
  text "6" at 336.182,-32.093 h1.78
M10 Fab Notes:
  drawing of 185 lines, arcs and shapes, not listed
  text "DESIGN INFORMATION" at 314.478,150.114 h0.8
  text "MIN. TRACK WIDTH:" at 298.106,145.542 h0.8
  text "8" at 325.951,145.542 h0.8
  text "MIL" at 329.881,145.542 h0.8
  text "MIN. CLEARANCE:" at 298.106,142.189 h0.8
  text "0.2" at 324.427,142.189 h0.8
  text "mm" at 329.881,142.189 h0.8
  text "MIN. VIA PAD SIZE:" at 298.106,138.836 h0.8
  text "24" at 325.189,138.836 h0.8
  text "MIL" at 329.881,138.836 h0.8
  text "0.05mm (2MIL)" at 315.759,135.237 h0.8
  text "MINIMUM ANNULAR RING" at 289.744,135.128 h0.8
  text "EXTERNAL" at 333.742,135.128 h0.8
  text "PER" at 294.824,132.131 h0.8
  text "IPC-D-275 CLASS 2 LEVEL C" at 300.412,132.131 h0.8
  text "MIL, HOLES" at 338.213,129.279 h0.8
  text "+/-" at 328.244,129.261 h0.8
  text "+/-" at 349.936,129.261 h0.8
  text "REGISTRATION TOLERANCES:" at 289.744,129.134 h0.8
  text "METAL" at 320.218,129.134 h0.8
  text "5" at 334.853,129.134 h0.8
  text "3" at 356.012,129.134 h0.8
  text "MIL" at 358.964,129.134 h0.8
  text "MATERIAL:" at 287.844,123.813 h0.8
  text "FR-4 High Tg" at 312.9,120.249 h0.8
  text "FR-408" at 298.538,120.031 h0.8
  text "X" at 309.003,120.031 h0.8
  text "OTHER" at 336.333,120.031 h0.8
  text "62 MIL (1.6mm) +/-10%" at 306.668,115.898 h0.8
  text "THICKNESS:" at 289.744,115.789 h0.8
  text "X" at 303.413,115.789 h0.8
  text "OTHER" at 339.305,115.789 h0.8
  text "TOLERANCE:" at 289.744,111.776 h0.8
  text "X" at 311.062,111.776 h0.8
  text "ANSI IPC-6012 TYPE 3 CLASS 2" at 315.81,111.776 h0.8
  text "OTHER +/-" at 315.81,107.814 h0.8
  text "BOW & TWIST:" at 289.744,103.826 h0.8
  text "X" at 311.062,103.826 h0.8
  text "ANSI IPC-6012 TYPE 3 CLASS 2" at 315.81,103.826 h0.8
  text "OTHER +/-" at 315.81,99.8 h0.8
  text "DRILLING:" at 287.844,96.282 h0.8
  text "REFERENCE:" at 289.744,93.31 h0.8
  text "X" at 306.209,93.31 h0.8
  text "AS SHOWN" at 310.958,93.31 h0.8
  text "X" at 329.094,93.31 h0.8
  text "NC_DRILL FILES" at 332.574,93.31 h0.8
  text "PTH MIN COPPER THICKNESS:" at 289.744,89.297 h0.8
  text "X" at 324.039,89.297 h0.8
  text "1MIL" at 327.519,89.297 h0.8
  text "OTHER" at 340.143,89.297 h0.8
  text "BOARD FINISH:" at 287.844,85.259 h0.8
  text "SILKSCREEN:" at 291.787,82.261 h0.8
  text "X" at 315.886,82.261 h0.8
  text "TOP" at 319.086,82.261 h0.8
  text "X" at 328.84,82.261 h0.8
  text "BOTTOM" at 332.066,82.261 h0.8
  text "SILKSCREEN COLOR:" at 291.787,78.02 h0.8
  text "X" at 315.86,78.02 h0.8
  text "WHITE" at 319.086,78.02 h0.8
  text "OTHER" at 332.066,78.02 h0.8
  text "SOLDER RESIST COLOR:" at 291.787,73.702 h0.8
  text "X" at 306.208,69.658 h0.8
  text "GREEN" at 309.434,69.658 h0.8
  text "BLUE" at 324.446,69.658 h0.8
  text "OTHER" at 338.111,69.658 h0.8
  text "IMMERSION GOLD (ENIG)" at 314.794,64.87 h0.8
  text "ENEPIG" at 348.767,64.786 h0.8
  text "SURFACE FINISH:" at 287.844,64.761 h0.8
  text "X" at 310.045,64.761 h0.8
  text "IMM. TIN/SILVER OR EQUIV" at 296.215,60.773 h0.8
  text "OTHER" at 332.574,60.773 h0.8
  text "ARRAY/PANEL:" at 287.844,56.226 h0.8
  text "CUT AND TRIM PER MECH LAYER 1" at 314.794,56.118 h0.8
  text "N.C. ROUTE" at 314.794,52.264 h0.8
  text "X" at 332.04,52.264 h0.8
  text "V. SCORE" at 336.79,52.264 h0.8
  text "CERTIFICATION:" at 287.844,48.784 h0.8
  text "MATERIALS AND WORKMANSHIP FOR ALL PCBS" at 306.259,48.784 h0.8
  text "TO MEET OR EXCEED THE REQUIREMENTS OF:" at 306.259,46.295 h0.8
  text "X" at 296.773,42.828 h0.8
  text "ANSI IPC-A-600F CLASS ->" at 300.303,42.828 h0.8
  text "X" at 341.935,42.828 h0.8
  text "2" at 344.956,42.828 h0.8
  text "1" at 336.955,42.79 h0.8
  text "3" at 353.948,42.79 h0.8
  text "X" at 296.825,38.777 h0.8
  text "UL 94V-0" at 300.303,38.777 h0.8
  text "X" at 317.45,38.777 h0.8
  text "RoHS" at 320.928,38.777 h0.8
  text "OTHER" at 337.296,38.777 h0.8
  text "PER ORDER" at 347.381,38.777 h0.8
  text "ADDITIONAL REQUIREMENTS:" at 287.844,35.195 h0.8
  text "MICROSECTION:" at 289.744,32.274 h0.8
  text "YES" at 312.749,32.274 h0.8
  text "REQUIRED" at 334.631,28.308 h0.8
  text "BARE BOARD ELEC. TEST:" at 289.744,28.236 h0.8
  text "NONE" at 322.909,28.236 h0.8
  text "X" at 331.405,28.236 h0.8
  text "PER ORDER" at 349.668,28.236 h0.8
  text "MANUFACTURER'S UL:" at 289.744,24.248 h0.8
  text "RAIL" at 319.353,24.139 h0.8
  text "METAL" at 331.845,24.139 h0.8
  text "X" at 341.376,24.13 h0.8
  text "SILK" at 344.842,24.139 h0.8
  text ".Layer_Name" at 14.656,-21.806 h0.8
M11 Gerber Information:
  lines w0.254: -7.417,-23.626 160.223,-23.626 ; -7.417,-18.462 160.274,-18.462 ; -7.417,-13.297 -7.417,-28.791 94.31,-28.791 160.274,-28.791 160.274,-13.297 -7.404,-13.297 -7.404,-28.791 32.614,-28.791 ; 55.194,-28.791 55.194,-13.297 ; 87.376,-18.462 87.376,-13.297 ; 108.712,-18.462 108.712,-13.297 ; 124.511,-28.956 124.511,-23.804
  text "ALL ARTWORK VIEWED FROM TOP SIDE" at -5.804,-16.654 h0.8
  text "BOARD #:" at 57.099,-16.654 h0.8
  text ".PRJ_Number" at 70.955,-16.654 h0.8
  text "REV:" at 92.405,-16.654 h0.8
  text ".PCB_Rev" at 99.809,-16.654 h0.8
  text "SVN REV:" at 113.69,-16.654 h0.8
  text ".VersionControl_RevNumber" at 126.543,-16.654 h0.8
  text "LAYER NAME =" at -5.804,-21.806 h0.8
  text "TID #:" at 57.099,-21.819 h0.8
  text ".TID" at 70.955,-21.819 h0.8
  text "PLOT NAME =" at -5.804,-27.034 h0.8
  text ".plot_File_Name" at 14.656,-27.034 h0.8
  text "GENERATED    :" at 57.15,-27.034 h0.8
  text ".Print_Date" at 79.235,-27.034 h0.8
  text ".Print_Time" at 97.752,-27.034 h0.8
  text "TEXAS INSTRUMENTS" at 129.87,-27.034 h0.8
M12 Stackup:
  text ".Layer_Name" at 14.656,-21.806 h0.8
M13 Component Bodies Top:
  text ".Layer_Name" at 14.656,-21.806 h0.8
M14 Component Bodies Bottom:
  text ".Layer_Name" at 14.656,-21.806 h0.8
M15 Courtyards Top:
  text ".Layer_Name" at 14.656,-21.806 h0.8
M16 Courtyards Bottom:
  text ".Layer_Name" at 14.656,-21.806 h0.8
Drill Drawing:
  drawing of 182 lines, arcs and shapes, not listed
  text "Symbol" at 202.441,123.275 h1.83
  text "Count" at 215.29,123.275 h1.83
  text "Hole Size" at 230.526,123.275 h1.83
  text "Plated" at 259.728,123.275 h1.83
  text "Hole Type" at 272.577,123.275 h1.83
  text "418" at 215.29,119.465 h1.52
  text "0.600mm (23.62mil)" at 230.526,119.465 h1.52
  text "PTH" at 259.728,119.465 h1.52
  text "Round" at 272.577,119.465 h1.52
  text "82" at 215.29,115.655 h1.52
  text "0.711mm (28.00mil)" at 230.526,115.655 h1.52
  text "PTH" at 259.728,115.655 h1.52
  text "Round" at 272.577,115.655 h1.52
  text "Q" at 201.702,115.401 h1.69
  text "38" at 215.29,111.845 h1.52
  text "0.200mm (7.87mil)" at 230.526,111.845 h1.52
  text "PTH" at 259.728,111.845 h1.52
  text "Round" at 272.577,111.845 h1.52
  text "12" at 215.29,108.035 h1.52
  text "0.900mm (35.43mil)" at 230.526,108.035 h1.52
  text "PTH" at 259.728,108.035 h1.52
  text "Round" at 272.577,108.035 h1.52
  text "U" at 201.702,107.781 h1.69
  text "12" at 215.29,104.225 h1.52
  text "1.016mm (40.00mil)" at 230.526,104.225 h1.52
  text "PTH" at 259.728,104.225 h1.52
  text "Round" at 272.577,104.225 h1.52
  text "J" at 201.702,103.971 h1.69
  text "12" at 215.29,100.415 h1.52
  text "1.400mm (55.12mil)" at 230.526,100.415 h1.52
  text "PTH" at 259.728,100.415 h1.52
  text "Round" at 272.577,100.415 h1.52
  text "8" at 215.29,96.605 h1.52
  text "1.100mm (43.31mil)" at 230.526,96.605 h1.52
  text "PTH" at 259.728,96.605 h1.52
  text "Round" at 272.577,96.605 h1.52
  text "A" at 201.702,96.351 h1.69
  text "8" at 215.29,92.795 h1.52
  text "5.400mm (212.60mil)" at 230.526,92.795 h1.52
  text "PTH" at 259.728,92.795 h1.52
  text "Round" at 272.577,92.795 h1.52
  text "6" at 215.29,88.985 h1.52
  text "1.650mm (64.96mil)" at 230.526,88.985 h1.52
  text "PTH" at 259.728,88.985 h1.52
  text "Round" at 272.577,88.985 h1.52
  text "6" at 215.29,85.175 h1.52
  text "2.000mm (78.74mil)" at 230.526,85.175 h1.52
  text "PTH" at 259.728,85.175 h1.52
  text "Round" at 272.577,85.175 h1.52
  text "D" at 201.702,84.921 h1.69
  text "6" at 215.29,81.365 h1.52
  text "3.150mm (124.02mil)" at 230.526,81.365 h1.52
  text "NPTH" at 259.728,81.365 h1.52
  text "Round" at 272.577,81.365 h1.52
  text "B" at 201.702,81.111 h1.69
  text "5" at 215.29,77.555 h1.52
  text "8.000mm (314.96mil)" at 230.526,77.555 h1.52
  text "NPTH" at 259.728,77.555 h1.52
  text "Round" at 272.577,77.555 h1.52
  text "4" at 215.29,73.745 h1.52
  text "1.450mm (57.09mil)" at 230.526,73.745 h1.52
  text "PTH" at 259.728,73.745 h1.52
  text "Round" at 272.577,73.745 h1.52
  text "4" at 215.29,69.935 h1.52
  text "1.550mm (61.02mil)" at 230.526,69.935 h1.52
  text "PTH" at 259.728,69.935 h1.52
  text "Round" at 272.577,69.935 h1.52
  text "4" at 215.29,66.125 h1.52
  text "1.750mm (68.90mil)" at 230.526,66.125 h1.52
  text "PTH" at 259.728,66.125 h1.52
  text "Round" at 272.577,66.125 h1.52
  text "3" at 215.29,62.315 h1.52
  text "1.850mm (72.84mil)" at 230.526,62.315 h1.52
  text "PTH" at 259.728,62.315 h1.52
  text "Round" at 272.577,62.315 h1.52
  text "E" at 201.702,62.061 h1.69
  text "2" at 215.29,58.505 h1.52
  text "0.406mm (16.00mil)" at 230.526,58.505 h1.52
  text "PTH" at 259.728,58.505 h1.52
  text "Round" at 272.577,58.505 h1.52
  text "V" at 201.702,58.251 h1.69
  text "2" at 215.29,54.695 h1.52
  text "0.750mm (29.53mil)" at 230.526,54.695 h1.52
  text "PTH" at 259.728,54.695 h1.52
  text "Round" at 272.577,54.695 h1.52
  text "2" at 215.29,50.885 h1.52
  text "1.000mm (39.37mil)" at 230.526,50.885 h1.52
  text "PTH" at 259.728,50.885 h1.52
  text "Round" at 272.577,50.885 h1.52
  text "O" at 201.702,50.631 h1.69
  text "2" at 215.29,47.075 h1.52
  text "1.090mm (42.91mil)" at 230.526,47.075 h1.52
  text "PTH" at 259.728,47.075 h1.52
  text "Round" at 272.577,47.075 h1.52
  text "2" at 215.29,43.265 h1.52
  text "1.150mm (45.28mil)" at 230.526,43.265 h1.52
  text "PTH" at 259.728,43.265 h1.52
  text "Round" at 272.577,43.265 h1.52
  text "2" at 215.29,39.455 h1.52
  text "1.200mm (47.24mil)" at 230.526,39.455 h1.52
  text "PTH" at 259.728,39.455 h1.52
  text "Round" at 272.577,39.455 h1.52
  text "2" at 215.29,35.645 h1.52
  text "1.600mm (62.99mil)" at 230.526,35.645 h1.52
  text "PTH" at 259.728,35.645 h1.52
  text "Round" at 272.577,35.645 h1.52
  text "R" at 201.702,35.391 h1.69
  text "2" at 215.29,31.835 h1.52
  text "2.650mm (104.33mil)" at 230.526,31.835 h1.52
  text "PTH" at 259.728,31.835 h1.52
  text "Slot" at 272.577,31.835 h1.52
  text "1" at 215.29,28.025 h1.52
  text "1.980mm (77.95mil)" at 230.526,28.025 h1.52
  text "PTH" at 259.728,28.025 h1.52
  text "Round" at 272.577,28.025 h1.52
  text "1" at 215.29,24.215 h1.52
  text "2.060mm (81.10mil)" at 230.526,24.215 h1.52
  text "PTH" at 259.728,24.215 h1.52
  text "Round" at 272.577,24.215 h1.52
  text "F" at 201.702,23.961 h1.69
  text "646 Total" at 215.29,20.405 h1.52
  text "Slot definitions :" at 202.441,16.723 h1.52
  text "Routed Path Length" at 228.671,16.723 h1.52
  text "= Calculated from tool start centre position to tool end centre position." at 256.679,16.723 h1.52
  text "Hole Length" at 228.671,14.183 h1.52
  text "= Routed Path Length + Tool Size = Slot length as defined in the PCB layout" at 246.268,14.183 h1.52
  text ".Layer_Name" at 14.656,-21.806 h0.8

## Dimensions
0,0 to 0,143 on M2 Board Dimensions
0,0 to 198,145 on M2 Board Dimensions
0,-10.16 to 25.4,-10.16 on M2 Board Dimensions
